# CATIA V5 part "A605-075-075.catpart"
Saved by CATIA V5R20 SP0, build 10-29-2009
Part number: A605-075-075
Source: Unknown
Property "A": "45.000"
Property "ARTICLENO": "A605-075-075"
Property "BOMINFO": "A605-075-075"
Property "CODE": "A605-075-075"
Property "D": "9.000"
Property "FORM": "C"
Property "L": "75.000"
Property "L1": "45.000"
Property "LINA": "A605-075-075"
Property "NB": "A605-075-075"
Property "NBSYN": "$CODE."
Property "NN": "A605"
Property "NT": "Wear Plates, self-lubricating"
Property "SCREW": "4*M8X16"
Property "SUPPLIER": "CF"
Property "W": "75.000"
Bounding box of the stored display mesh (mm): x -75 to 0, y 0 to 5, z -75 to 0
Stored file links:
  C:\Users\Utente\Desktop\3D files A605\A605-075-075.catpart
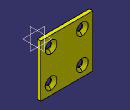
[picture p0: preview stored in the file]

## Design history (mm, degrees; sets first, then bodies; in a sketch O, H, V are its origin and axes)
Body1 "Geometry.1" (main body)
  Solid1 "A605-075-075.catpart": solid without history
